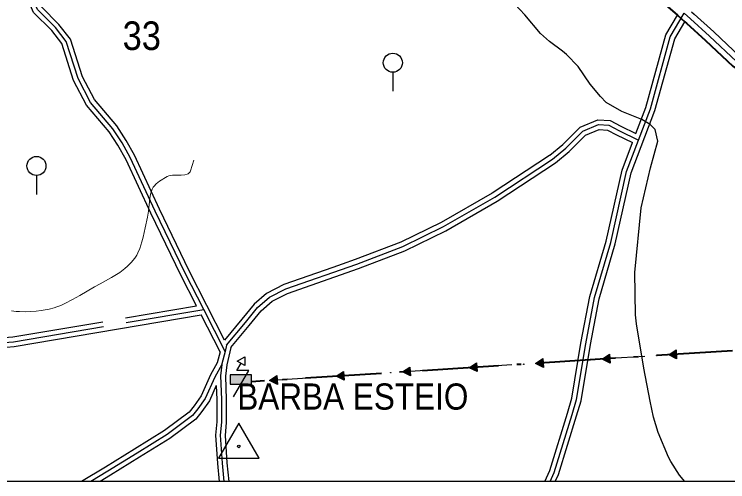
# Model space of a CAD drawing. Extents: x -64005 to -55000, y -89025 to -80000.
# Drawn here: x -59654 to -58155, y -89000 to -88019 of the extents above; entities that cross this region are included whole.
import ezdxf
from ezdxf.enums import TextEntityAlignment as Align

# ---------------------------------------------------------------- set-up
doc = ezdxf.new("R2010")
doc.units = 0
doc.header["$LTSCALE"] = 32
doc.linetypes.add('DOT_DASHED', pattern=[7.7, 5, -1.2, 0.3, -1.2])
doc.linetypes.add('LONG_DASHED', pattern=[7.5, 6, -1.5])
for name, color, linetype, lineweight in [('1', 7, 'Continuous', 25), ('18', 7, 'Continuous', 25), ('2', 7, 'Continuous', 25), ('24', 7, 'Continuous', 25), ('32', 7, 'Continuous', 25), ('39', 7, 'LONG_DASHED', 25), ('41', 7, 'Continuous', 25), ('5', 7, 'Continuous', 40), ('8', 7, 'Continuous', 25)]:
    doc.layers.add(name, color=color, linetype=linetype, lineweight=lineweight)
doc.layers.add('36', color=7, linetype='Continuous')
doc.layers.add('38', color=7, linetype='Continuous')

msp = doc.modelspace()

# ---------------------------------------------------------------- hatches: boundary and pattern name
at = {"layer": '18'}
for points in [[(-58262.73, -88741.9), (-58279.31, -88733.7), (-58263.91, -88723.44)], [(-58542.15, -88759.87), (-58558.73, -88751.67), (-58543.34, -88741.41)], [(-58402.44, -88750.88), (-58419.02, -88742.68), (-58403.63, -88732.42)], [(-58821.57, -88777.84), (-58838.15, -88769.64), (-58822.76, -88759.38)], [(-58681.86, -88768.85), (-58698.44, -88760.65), (-58683.05, -88750.39)], [(-58961.28, -88786.82), (-58977.86, -88778.62), (-58962.47, -88768.36)], [(-59200.46, -88795.33), (-59155.46, -88795.33), (-59155.46, -88775.33), (-59200.46, -88775.33)], [(-59100.99, -88795.81), (-59117.58, -88787.61), (-59102.18, -88777.35)]]:
    msp.add_hatch(color=256, dxfattribs=at).paths.add_polyline_path(points)

# ---------------------------------------------------------------- linework, layer by layer
at = {"layer": '1'}
for points in [[(-58422.27, -88191.35), (-58444.45, -88165.65), (-58469.71, -88128.35), (-58494.02, -88103.43), (-58502.62, -88096.15), (-58529.83, -88075.88), (-58548.86, -88059.21), (-58581.45, -88020.12), (-58602.83, -87997.7)], [(-58245.69, -88999.4), (-58256.39, -88985.92), (-58274.71, -88957.74), (-58279.4, -88948.38), (-58301.21, -88896.89), (-58311.01, -88864.34), (-58318.27, -88831.02), (-58331.57, -88761.9), (-58346.92, -88668.49), (-58348.77, -88649.43), (-58350.6, -88560.93), (-58337.02, -88424.99), (-58317.17, -88340.88), (-58301.99, -88284.81), (-58307.83, -88260.27), (-58318.34, -88249.76), (-58336.03, -88239.68), (-58377.71, -88222.85), (-58410.95, -88203.62), (-58422.27, -88191.35)]]:
    msp.add_lwpolyline(points, dxfattribs=at)
at = {"layer": '18'}
for p, q in [((-58189.49, -88727.92), (-58263.32, -88732.67)), ((-58329.2, -88736.9), (-58403.03, -88741.65)), ((-58608.63, -88754.88), (-58682.45, -88759.62)), ((-58468.92, -88745.89), (-58542.74, -88750.64)), ((-58888.05, -88772.85), (-58961.88, -88777.59)), ((-58748.34, -88763.86), (-58822.17, -88768.61)), ((-59027.76, -88781.83), (-59101.59, -88786.58))]:
    msp.add_line(p, q, dxfattribs=at)
at = {"layer": '18', "linetype": 'DOT_DASHED', "lineweight": 40}
msp.add_lwpolyline([(-55785.61, -89000), (-55892.77, -88968.32), (-56019.51, -88930.17), (-56280.02, -88850.32), (-56575.76, -88760.83), (-56782.32, -88697.86), (-56995.51, -88708.52), (-57161.56, -88661.81), (-59155.46, -88790.04)], dxfattribs=at)
at = {"layer": '18'}
for points in [[(-58262.73, -88741.9), (-58279.31, -88733.7), (-58263.91, -88723.44)], [(-59185.7, -88746.84), (-59169.68, -88737.58), (-59169.68, -88756.08)], [(-58542.15, -88759.87), (-58558.73, -88751.67), (-58543.34, -88741.41)], [(-58402.44, -88750.88), (-58419.02, -88742.68), (-58403.63, -88732.42)], [(-58821.57, -88777.84), (-58838.15, -88769.64), (-58822.76, -88759.38)], [(-58681.86, -88768.85), (-58698.44, -88760.65), (-58683.05, -88750.39)], [(-58961.28, -88786.82), (-58977.86, -88778.62), (-58962.47, -88768.36)], [(-59200.46, -88795.33), (-59155.46, -88795.33), (-59155.46, -88775.33), (-59200.46, -88775.33)], [(-59100.99, -88795.81), (-59117.58, -88787.61), (-59102.18, -88777.35)]]:
    msp.add_lwpolyline(points, close=True, dxfattribs=at)
msp.add_lwpolyline([(-59193.26, -88821.83), (-59161.57, -88766.83), (-59186.57, -88766.83), (-59177.69, -88751.46)], dxfattribs=at)
for centre in [(-58164.54, -88726.32), (-58443.97, -88744.29), (-58304.25, -88735.3), (-58583.68, -88753.27), (-58863.1, -88771.24), (-58723.39, -88762.26), (-59142.52, -88789.21), (-59002.81, -88780.23)]:
    msp.add_circle(centre, 0.5, dxfattribs=at)
at = {"layer": '2', "lineweight": 13}
msp.add_lwpolyline([(-59277.18, -88325.26), (-59283.95, -88347.47), (-59284.59, -88349.14), (-59286.43, -88351.82), (-59288.94, -88353.76), (-59290.93, -88354.68), (-59295.56, -88355.83), (-59303.67, -88356.32), (-59315.49, -88356.2), (-59321.32, -88356.44), (-59326.77, -88357.28), (-59329.3, -88358), (-59332.74, -88359.58), (-59348.75, -88369.16), (-59356.02, -88374.86), (-59360.17, -88379.33), (-59361.97, -88381.82), (-59364.25, -88385.92), (-59366.73, -88392.28), (-59367.94, -88396.58), (-59369.57, -88405.29), (-59371.85, -88431.7), (-59373.17, -88440.38), (-59374.18, -88444.66), (-59379.18, -88466.75), (-59383.31, -88486.58), (-59385.75, -88496.36), (-59390.43, -88510.65), (-59394.49, -88519.82), (-59396.88, -88524.27), (-59400.96, -88530.75), (-59408.39, -88539.96), (-59416.15, -88547.62), (-59421.51, -88552.24), (-59432.6, -88560.53), (-59449.95, -88571.27), (-59473.81, -88584.28), (-59485.8, -88591.04), (-59516.4, -88609.02), (-59531.9, -88617.63), (-59548.1, -88625.87), (-59556.59, -88629.83), (-59564.65, -88633.12), (-59570.05, -88634.98), (-59580.93, -88637.96), (-59597.36, -88640.89), (-59608.34, -88642.04), (-59630.22, -88643.08), (-59643.38, -88642.99), (-59649.96, -88642.58), (-59659.81, -88641.38)], dxfattribs=at)
at = {"layer": '24'}
msp.add_lwpolyline([(-56798.81, -88651.21), (-56747.66, -88705.55), (-56673.35, -88780.64), (-56593, -88853.12), (-56498.33, -88935.21), (-56420.71, -88999.21), (-61547.64, -88999.74)], dxfattribs=at)
at = {"layer": '32'}
for p, q in [((-58858.83, -88140.38), (-58858.83, -88180.38)), ((-59607.41, -88357.15), (-59607.41, -88397.15))]:
    msp.add_line(p, q, dxfattribs=at)
for centre in [(-58858.83, -88120.38), (-59607.41, -88337.15)]:
    msp.add_circle(centre, 20, dxfattribs=at)
at = {"layer": '39'}
for points in [[(-59256.17, -88638.55), (-59295.32, -88561.98), (-59358.09, -88431.71), (-59410.32, -88319.47), (-59427.49, -88288.86), (-59446.73, -88259.27), (-59494.1, -88203.58), (-59520.16, -88153.82), (-59545.03, -88075.62), (-59567.77, -88046.45), (-59605.25, -88008.97), (-59613.46, -87989.81), (-59613.71, -87959.51), (-59595.95, -87909.73), (-59592.33, -87871.59)], [(-58342.56, -88282.98), (-58317.71, -88217.55), (-58275.99, -88066.09), (-58246.87, -88016.59)], [(-58523.43, -88323.01), (-58495.09, -88299.68), (-58459.52, -88264.11), (-58426.69, -88250.43), (-58404.8, -88251.78), (-58384.27, -88262.73), (-58342.56, -88282.98)], [(-58528.49, -88999.43), (-58519.73, -88980.63), (-58482.29, -88858.81), (-58472.86, -88827.29), (-58453.65, -88710.66), (-58435.26, -88613.45), (-58401.13, -88497.84), (-58367.6, -88348.92), (-58342.56, -88282.98)], [(-59208.2, -88713.65), (-59168.57, -88665.61), (-59142.84, -88633.99), (-59118.06, -88612.82), (-59083.68, -88595.4), (-58934.33, -88543.22), (-58837.77, -88506.14), (-58752.45, -88464.56), (-58644.67, -88402.77), (-58523.43, -88323.01)], [(-59755.33, -88587.7), (-59743.49, -88612.45), (-59734.01, -88634.96), (-59710.33, -88688.27), (-59700.86, -88701.3), (-59685.47, -88708.41), (-59655.85, -88706.03), (-59256.17, -88638.55)], [(-59208.2, -88713.65), (-59211.28, -88726.36), (-59256.17, -88638.55)], [(-59211.28, -88726.36), (-59217.69, -88752.79), (-59217.83, -88754)], [(-59217.83, -88754), (-59232.79, -88780.4), (-59252.86, -88824.99), (-59268.12, -88846.67), (-59279.76, -88861.13), (-59332.76, -88900.88), (-59396.19, -88940.24), (-59457.22, -88977.99), (-59493.23, -88999.53)], [(-59217.83, -88754), (-59220.59, -88777.81), (-59218.78, -88827.51), (-59218.78, -88875.04), (-59221.32, -88902.61), (-59217.33, -88961.08), (-59213.53, -88999.5)]]:
    msp.add_lwpolyline(points, dxfattribs=at)
at = {"layer": '39', "lineweight": 35}
msp.add_lwpolyline([(-58246.87, -88016.59), (-58233.78, -88028.13), (-58193.22, -88064.51), (-58136.94, -88117.65), (-58080.08, -88155.27), (-58017.22, -88193.57), (-57965.64, -88220.02), (-57878.79, -88263), (-57771.46, -88314.19), (-57685.05, -88348.91), (-57522.45, -88430.26), (-57438.68, -88470.35), (-57223.79, -88577.19), (-57140.91, -88616.87), (-57004.64, -88685.19)], dxfattribs=at)
at = {"layer": '41'}
msp.add_lwpolyline([(-59182.35, -88876.95), (-59224.85, -88950.56), (-59139.85, -88950.56)], close=True, dxfattribs=at)
msp.add_circle((-59182.35, -88926.02), 2.5, dxfattribs=at)
at = {"layer": '5'}
for points in [[(-59432.95, -86979.11), (-59383.8, -87023), (-59282.96, -87110.49), (-59223.68, -87164.38), (-59176.42, -87207.85), (-59086.89, -87286.39), (-59001.12, -87362.36), (-58930.04, -87425.26), (-58859.79, -87485.28), (-58807.48, -87535.56), (-58728.45, -87607.95), (-58577.32, -87740.19), (-58524.91, -87786.44), (-58417.83, -87882.24), (-58370.64, -87923.59), (-58286.15, -87998.63), (-58260.96, -88020.83), (-58245.68, -88034.3)], [(-58245.68, -88034.3), (-58242.09, -88037.47), (-58201.69, -88073.71), (-58144.74, -88127.48), (-58086.78, -88165.82), (-58023.33, -88204.48), (-57971.27, -88231.18), (-57884.25, -88274.24), (-57776.49, -88325.64), (-57690.19, -88360.32), (-57527.95, -88441.49), (-57444.16, -88481.58), (-57229.27, -88588.42), (-57146.41, -88628.09), (-56982.82, -88710.11), (-56928.62, -88738.39), (-56896.63, -88757.84), (-56870.83, -88775.54), (-56833.24, -88804.15)]]:
    msp.add_lwpolyline(points, dxfattribs=at)
at = {"layer": '5', "lineweight": 25}
msp.add_lwpolyline([(-58231.45, -88013.52), (-58225.47, -88018.79), (-58184.75, -88055.3), (-58129.14, -88107.82), (-58073.37, -88144.72), (-58011.11, -88182.66), (-57960.01, -88208.86), (-57873.33, -88251.76), (-57766.43, -88302.74), (-57679.91, -88337.5), (-57516.95, -88419.03), (-57433.2, -88459.12), (-57218.31, -88565.96), (-57135.41, -88605.65), (-57006.45, -88670.3)], dxfattribs=at)
at = {"layer": '8'}
for q in [(-59261.74, -88649.63), (-59227.48, -88750.76)]:
    msp.add_line((-59221.87, -88727.61), q, dxfattribs=at)
at = {"layer": '8', "linetype": 'LONG_DASHED'}
for points in [[(-59271.29, -88630.96), (-59304.28, -88566.43), (-59367.17, -88435.91), (-59419.04, -88324.36), (-59436.22, -88293.75), (-59454.63, -88265.42), (-59502.44, -88209.21), (-59529.42, -88157.68), (-59554.13, -88079.99), (-59575.28, -88053.08), (-59613.68, -88014.68), (-59623.44, -87991.9), (-59624.03, -87958.67), (-59623.67, -87957.65)], [(-58348.03, -88269.21), (-58327.23, -88214.44), (-58285.28, -88062.16), (-58260.96, -88020.83)], [(-58528.97, -88314.61), (-58501.82, -88292.27), (-58465.19, -88255.64), (-58428.39, -88240.31), (-58402, -88241.93), (-58379.73, -88253.82), (-58348.03, -88269.21)], [(-58539.52, -88999.43), (-58528.79, -88976.41), (-58491.87, -88855.94), (-58482.44, -88824.42), (-58463.56, -88709.22), (-58444.99, -88611.1), (-58410.81, -88495.32), (-58377.2, -88346.03), (-58355.16, -88287.99)], [(-58528.97, -88314.61), (-58529.4, -88314.97), (-58529.82, -88315.25), (-58649.91, -88394.25), (-58757.13, -88455.72), (-58841.76, -88496.96), (-58937.77, -88533.83), (-58965.11, -88543.38), (-58984.68, -88550.23), (-59087.6, -88586.18), (-59124.1, -88604.67), (-59150.02, -88626.97), (-59176.05, -88658.96), (-59212.14, -88702.71)], [(-59683.66, -88698.22), (-59657.08, -88696.1), (-59271.29, -88630.96)], [(-59227.48, -88750.76), (-59241.72, -88775.87), (-59261.59, -88820.01), (-59276.11, -88840.65), (-59286.76, -88853.88), (-59338.41, -88892.62), (-59401.46, -88931.74), (-59462.43, -88969.45), (-59512.71, -88999.53)], [(-59229.85, -88798.25), (-59228.78, -88827.69), (-59228.78, -88874.58), (-59231.35, -88902.49), (-59227.3, -88961.91), (-59223.58, -88999.5)]]:
    msp.add_lwpolyline(points, dxfattribs=at)
at = {"layer": '8'}
for points in [[(-59212.14, -88702.71), (-59286.36, -88557.52), (-59349.01, -88427.5), (-59401.6, -88314.56), (-59418.77, -88283.96), (-59438.82, -88253.11), (-59485.76, -88197.95), (-59510.9, -88149.96), (-59535.93, -88071.25), (-59560.26, -88039.82), (-59596.82, -88003.26), (-59603.48, -87987.72), (-59603.39, -87960.35), (-59603.09, -87959.51)], [(-58517.46, -88999.43), (-58510.67, -88984.86), (-58472.71, -88861.68), (-58463.28, -88830.16), (-58443.74, -88712.1), (-58425.53, -88615.8), (-58391.45, -88500.36), (-58358, -88351.8), (-58308.19, -88220.66), (-58266.69, -88070.02), (-58245.68, -88034.3)], [(-58517.07, -88330.73), (-58488.36, -88307.09), (-58453.85, -88272.58), (-58424.99, -88260.55), (-58407.59, -88261.64), (-58388.81, -88271.64), (-58355.16, -88287.99)], [(-59199.01, -88718.24), (-59160.83, -88671.95), (-59135.66, -88641.01), (-59112.47, -88621.2), (-59079.76, -88604.62), (-58930.89, -88552.61), (-58833.78, -88515.32), (-58747.77, -88473.4), (-58639.43, -88411.29), (-58517.07, -88330.73)], [(-59687.27, -88718.59), (-59654.62, -88715.96), (-59261.74, -88649.63)], [(-59199.01, -88718.24), (-59207.83, -88754.55), (-59210.57, -88778.21), (-59208.78, -88827.33), (-59208.78, -88875.5), (-59211.29, -88902.73), (-59207.36, -88960.25), (-59203.48, -88999.5)], [(-59229.85, -88798.25), (-59244.13, -88829.97), (-59260.13, -88852.69), (-59272.76, -88868.38), (-59327.11, -88909.14), (-59390.92, -88948.74), (-59452.02, -88986.53), (-59473.75, -88999.53)]]:
    msp.add_lwpolyline(points, dxfattribs=at)

# ---------------------------------------------------------------- texts
at = {"layer": '36', "width": 0.9}
msp.add_text('BARBA ESTEIO', height=55, dxfattribs=at).set_placement((-58942.85, -88848.68), align=Align.CENTER)
at = {"layer": '38', "width": 0.9}
msp.add_text('33', height=60, rotation=0.007, dxfattribs=at).set_placement((-59386.25, -88093.7), align=Align.CENTER)

doc.saveas('drawing.dxf')
